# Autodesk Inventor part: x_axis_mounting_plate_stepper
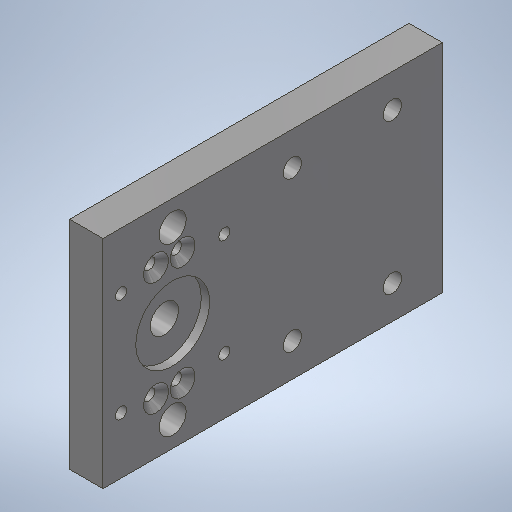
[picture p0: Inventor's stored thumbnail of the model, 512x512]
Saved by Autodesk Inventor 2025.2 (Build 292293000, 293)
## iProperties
Created: 2025-04
Part Number: x_axis_mounting_plate_stepper
Material: 1.0037 S235JR
Document SubType Name: Modeling
Designer: BennF
Density: 7.85 g/cm^3
Appearance: Stahl
Author: BennF
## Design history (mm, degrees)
sketch "Sketch2"
  geometry: L1 (50.9, 32.5)-(-50.9, 32.5); L2 (-50.9, 32.5)-(-50.9, -32.5); L3 (-50.9, -32.5)-(50.9, -32.5); L4 (50.9, -32.5)-(50.9, 32.5); 3 further points
  constraints: 8 end point, 2 midpoint, 2 parallel, 1 horizontal, 1 horizontal alignment, 1 perpendicular, 1 vertical alignment
  dimensions: "d0" = 101.8 distance of L1.start L1.end; "d1" = 65 distance of L1.end L2.end
extrude "Extrusion1" new body sketch "Sketch2" distance "d2" = 10; taper "d3" = 0 deg
sketch "Sketch3"
  geometry: L1 (15.5, -14.5)-(-15.5, -14.5); L2 (-15.5, -14.5)-(-15.5, -45.5); L3 (-15.5, -45.5)-(15.5, -45.5); L4 (15.5, -45.5)-(15.5, -14.5); L5 (32.5, -50.9)-(-32.5, -50.9) reference; 4 further points
  constraints: 8 end point, 2 coincident, 2 parallel, 2 perpendicular, 1 horizontal, 1 midpoint, 1 vertical alignment
  dimensions: "d11" = 31 distance of L3.end L1.start; "d12" = 5.4 distance from line of L5 L3.end
hole "Hole1" sketch "Sketch3" at (15.5, -45.5), (-15.5, -14.5), (-15.5, -45.5), (15.5, -14.5) diameter "d4" = 3.4; stored, may be unused: countersink angle "d8" = 90 deg, drill point angle "d10" = 118 deg; dims "d5" = 6, "d6" = 7.5, "d7" = 2, "d9" = 8
workplane "Work Plane1"
sketch "Sketch4"
  geometry: L1 (10, 0)-(10, 65) reference; L2 (10, 43.575)-(7.5, 43.575); L3 (7.5, 43.575)-(7.5, 36.75); L4 (7.5, 36.75)-(0, 36.75); L5 (0, 32.5)-(10, 32.5); L6 (10, 0)-(0, 0) reference; L7 (0, 0)-(0, 65) reference; L8 (0, 65)-(10, 65) reference; L9 (10, 65)-(10, 0) reference
  constraints: 8 end point, 2 perpendicular, 1 horizontal, 1 midpoint, 1 point on line
  dimensions: "d14" = 22.15 diameter of L2 L5; "d15" = 8.5 diameter of L4 L5; "d16" = 2.5 distance between parallel lines of L1 L3
revolve "Revolution1" sketch "Sketch4" stored, may be unused: angle "d17" = 90 deg
sketch "Sketch5"
  geometry: L1 (25, -30)-(-25, -30); C1 r 4.075 at (25, -30); C2 r 4.075 at (-25, -30); C3 r 4.25 at (0, -30) reference; 2 further points
  constraints: 2 centre point, 2 end point, 1 coincident, 1 equal radius, 1 horizontal, 1 midpoint
  dimensions: "d18" = 8.15 diameter of C1; "d19" = 50 distance of L1.start L1.end
extrude "Extrusion2" cut sketch "Sketch5" stored distance "d20" = 5; taper "d21" = 0 deg
sketch "Sketch6"
  geometry: L1 (22.5, 35.9)-(-22.5, 35.9); L2 (-32.5, 50.9)-(32.5, 50.9) reference; 4 further points
  constraints: 3 vertical alignment, 2 end point, 1 horizontal, 1 horizontal alignment, 1 midpoint
  dimensions: "d29" = 45 distance of L1.start L1.end; "d30" = 15 distance between parallel lines of L2 L1; "d41" = 30 distance of point (22.5, 5.9) L1.start
hole "Hole2" sketch "Sketch6" at (22.5, 35.9), (-22.5, 35.9), (22.5, 5.9), (-22.5, 5.9) diameter "d22" = 5.5; stored, may be unused: countersink angle "d26" = 90 deg, drill point angle "d28" = 118 deg; dims "d23" = 6, "d24" = 12.5, "d25" = 2, "d27" = 8
sketch "Sketch7"
  geometry: L1 (-17, -35)-(-17, -27); C1 r 4.075 at (-25, -30) reference; 1 further point
  constraints: 2 end point, 1 vertical, 1 vertical alignment
  dimensions: "d38" = 8 distance from line of L1 C1.centre; "d39" = 8 distance of L1.start L1.end; "d40" = 5 vertical distance of C1.centre L1.start
hole "Hole3" sketch "Sketch7" at (-17, -27), (-17, -35) diameter "d31" = 3.4; stored, may be unused: countersink angle "d35" = 90 deg, drill point angle "d37" = 0 deg; dims "d32" = 10 (= d2), "d33" = 7.5, "d34" = 3.4, "d36" = 8
workplane "Work Plane2"
mirror "Mirror1"
body "Solid1"
node "Project Cut Edges1"
other parameters: "d13" = -20.9 (= -d12 - 0.5 x d11)
